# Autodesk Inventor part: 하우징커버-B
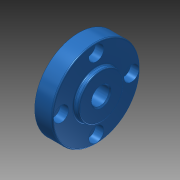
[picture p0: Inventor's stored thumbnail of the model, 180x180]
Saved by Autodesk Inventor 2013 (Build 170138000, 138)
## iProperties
Created: 2018-01
Part Number: 하우징커버-B
Material: 알루미늄 6061
Document SubType Name: Modeling
Designer: mduedu
Density: 2.71 g/cm^3
Mass: 17.2512 g
Surface Area: 32.1467 cm^2
Volume: 6.36575 cm^3
Author: mduedu
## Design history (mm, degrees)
sketch "스케치1"
  geometry: C1 r 17.5 at (0, 0); 1 further point
  constraints: 1 centre point, 1 coincident
  dimensions: "d0" = 35 diameter of C1
extrude "돌출1" new body sketch "스케치1" distance "d1" = 7; taper "d2" = 0 deg
sketch "스케치2"
  geometry: C1 r 9 at (0, 0); 1 further point
  constraints: 1 centre point, 1 coincident
  dimensions: "d3" = 18 diameter of C1
extrude "돌출2" join sketch "스케치2" distance "d4" = 2; taper "d5" = 0 deg
fillet "모깎기1" dims "d6" = 0.5
fillet "모깎기2" dims "d7" = 0.5
hole "구멍1" diameter "d10" = 7; stored, may be unused: countersink angle "d14" = 90 deg, drill point angle "d16" = 118 deg; dims "d8" = 10, "d9" = 10, "d11" = 6, "d12" = 4, "d13" = 2, "d15" = 8
chamfer "모따기1" distance "d17" = 0.5; stored, may be unused: second distance "d18" = 2, angle "d19" = 45 deg
sketch "스케치3" dims "d21" = 25
  geometry: 6 further points
  constraints: 2 vertical alignment, 1 coincident, 7 other
  dimensions: "d24" = 360 deg dimension on point (0, 0) point (0, 12.5) (derived)
sketch "스케치4"
  geometry: C1 r 17.5 at (0, 0) reference; A1 r 14 centre (0, 0) between (0, 14) and (-14, 0); 2 further points
  constraints: 4 point on circle, 2 horizontal alignment, 2 vertical alignment, 1 centre point, 1 coincident
  dimensions: "d34" = 28 diameter of A1
hole "구멍2" sketch "스케치4" at (-14, 0), (0, -14), (14, 0), (0, 14) diameter "d26" = 3.4; stored, may be unused: countersink angle "d30" = 90 deg, drill point angle "d32" = 0 deg; dims "d27" = 6, "d28" = 6, "d29" = 3.5, "d31" = 8
node "솔리드1"
